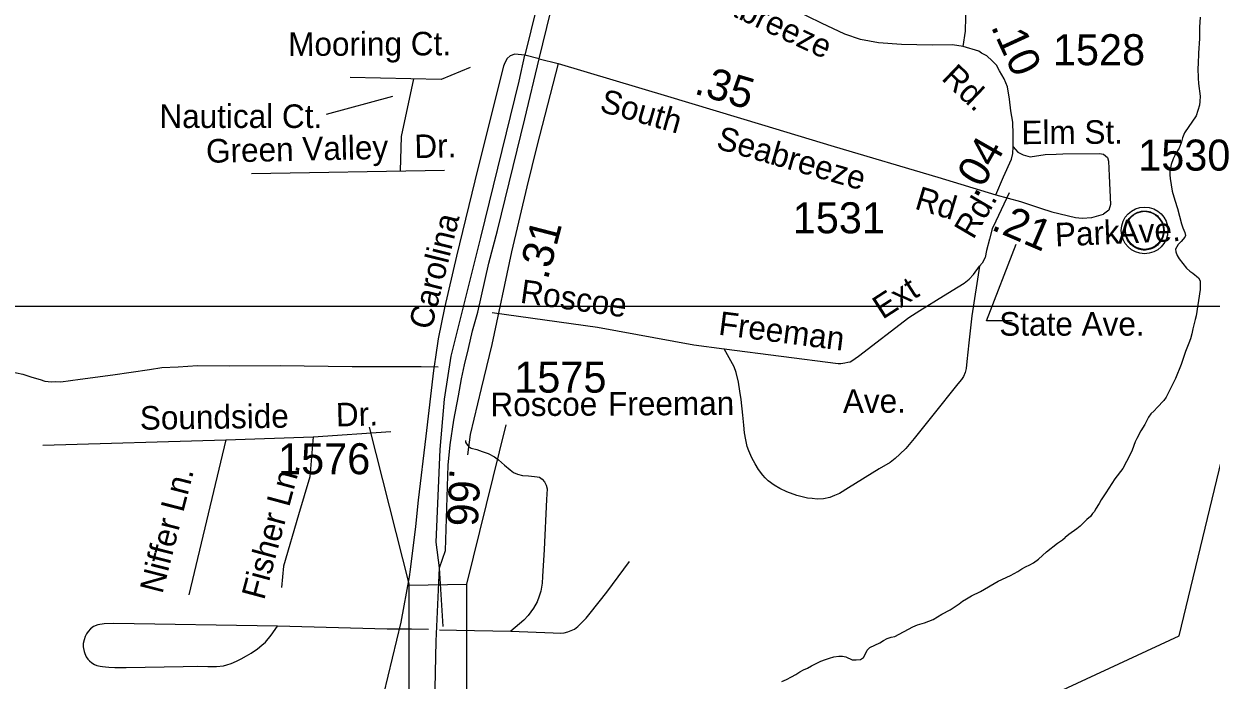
# Model space of a CAD drawing. Extents: x 2290055 to 2389491, y 66597 to 237875.
# Drawn here: x 2331660 to 2336448, y 113874 to 116521 of the extents above; entities that cross this region are included whole.
import ezdxf

# ---------------------------------------------------------------- set-up
doc = ezdxf.new("R2010")
doc.units = 0
for name, color, linetype in [('Exist Boundary Political City Limit New', 7, 'Continuous'), ('Exist Civil Demographics Community CELL', 7, 'Continuous'), ('Exist Hydrographic Island Shore', 7, 'Continuous'), ('Exist Road Non-System Type 51', 7, 'Continuous'), ('Exist Road Non-System Type 51 Label', 7, 'Continuous'), ('Exist Road Primary US Divided Attributed', 7, 'Continuous'), ('Exist Road Primary US Label', 7, 'Continuous'), ('Exist Road Primary US Mileage Hundredths English Label', 7, 'Continuous'), ('Exist Road Primary US Structure Standard Bridge CELL', 7, 'Continuous'), ('Exist Road Primary US UnDivided 4 Lane Attributed', 7, 'Continuous'), ('Exist Road Secondary Mileage Hundredths English Label', 7, 'Continuous'), ('Exist Road Secondary Type 51 Attributed', 7, 'Continuous'), ('Exist Road Secondary Type 51 Label', 7, 'Continuous'), ('Exist Road Secondary Type 51 Number Label', 7, 'Continuous'), ('Map Preparation Boundary City Limit Buffer Line', 7, 'Continuous'), ('Map Preparation Inset Cut Line', 7, 'Continuous')]:
    doc.layers.add(name, color=color, linetype=linetype)

msp = doc.modelspace()

# ---------------------------------------------------------------- linework, layer by layer
at = {"layer": 'Exist Boundary Political City Limit New'}
msp.add_lwpolyline([(2330352.2, 107963.5), (2330441, 107913.5), (2331723, 108557.6), (2331795.2, 108507.7), (2332822, 112811.2), (2334428.5, 113377.6), (2334989.2, 113572), (2335533.8, 113689.2), (2336319, 114052.8), (2336557, 115038.5), (2336580.2, 115183.5), (2339245, 115328.5)], dxfattribs=at)
at = {"layer": 'Exist Civil Demographics Community CELL'}
msp.add_lwpolyline([(2336101.6, 115700), (2336102.6, 115705.6), (2336104.3, 115712.2), (2336107.3, 115719.4), (2336110.2, 115725.1), (2336113.5, 115730.8), (2336117.3, 115736), (2336121.2, 115740.3), (2336125.8, 115744.9), (2336131.4, 115749.5), (2336136.8, 115753.2), (2336141.7, 115756), (2336146.7, 115758.5), (2336152.2, 115760.8), (2336157.8, 115762.6), (2336162.2, 115763.8), (2336167, 115764.5), (2336171.1, 115765.2), (2336177.5, 115765.5), (2336181.9, 115765.4), (2336187.6, 115765.1), (2336192.5, 115764.4), (2336197.4, 115763.4), (2336202.4, 115762), (2336207.6, 115760.1), (2336214.2, 115757.1), (2336220.5, 115753.6), (2336225.6, 115750.1), (2336230.7, 115746.1), (2336234, 115742.9), (2336238.2, 115738.6), (2336242, 115733.9), (2336245.1, 115729.3), (2336248.2, 115724.3), (2336250.7, 115719.1), (2336252.7, 115714.1), (2336254.3, 115709.1), (2336255.6, 115704.5), (2336256.6, 115698.4), (2336257.3, 115693.7), (2336257.5, 115687.7), (2336257.4, 115681.9), (2336256.8, 115676.3), (2336255.8, 115670.8), (2336254.2, 115664.6), (2336252.3, 115658.8), (2336250, 115653.7), (2336246.9, 115647.7), (2336243.6, 115642.4), (2336240.1, 115637.7), (2336235.9, 115632.9), (2336230.6, 115628), (2336225.6, 115623.9), (2336220.6, 115620.4), (2336216.3, 115617.9), (2336209.5, 115614.7), (2336202.3, 115612), (2336196.4, 115610.5), (2336189.8, 115609.2), (2336185.3, 115608.7), (2336180.8, 115608.5), (2336175.3, 115608.5), (2336171, 115608.9), (2336165.3, 115609.6), (2336159.4, 115610.9), (2336154.8, 115612.2), (2336149.7, 115614.1), (2336145.1, 115616.1), (2336141.2, 115618.3), (2336134.3, 115622.4), (2336128.8, 115626.7), (2336123.9, 115631.2), (2336119.4, 115636), (2336116.2, 115640), (2336113.2, 115644.2), (2336109.1, 115651.3), (2336107.4, 115654.8), (2336105.7, 115658.8), (2336103.1, 115667), (2336101.6, 115674.1), (2336100.9, 115679.2), (2336100.6, 115685.5), (2336100.5, 115690.2), (2336101.1, 115696.7)], close=True, dxfattribs=at)
for centre, radius in [((2336179.2, 115687.6), 94.3), ((2336178.9, 115687.9), 76.7)]:
    msp.add_circle(centre, radius, dxfattribs=at)
at = {"layer": 'Exist Hydrographic Island Shore'}
for points in [[(2336403.2, 116546.9), (2336400.5, 116507), (2336401.2, 116461.6), (2336397, 116401.8), (2336394.7, 116359.6), (2336394.5, 116341.5), (2336394.7, 116300.9), (2336396.5, 116279.8), (2336403.2, 116229.3), (2336402.5, 116207.8), (2336400, 116191.9), (2336386.5, 116149.7), (2336340.5, 116080.3), (2336332, 116061.3), (2336327.5, 116044.1), (2336318.7, 116019.6), (2336306.2, 116000), (2336294.2, 115976.5), (2336286, 115953.7), (2336281.5, 115928), (2336281.5, 115912.2), (2336282.7, 115896.6), (2336290, 115846.4), (2336301, 115809), (2336312, 115776.2), (2336328.2, 115713.9), (2336333.7, 115697.9), (2336341.2, 115679.7), (2336343.5, 115667.7), (2336341.7, 115659.7), (2336326.5, 115642.4), (2336315, 115631.4), (2336303.2, 115612.2), (2336304.5, 115601.1), (2336310.5, 115587), (2336318.5, 115572.8), (2336348.5, 115535.8), (2336361.5, 115523.6), (2336374, 115514.9), (2336397, 115496.6), (2336403, 115484.2), (2336402.7, 115449.9), (2336386.5, 115343), (2336383.2, 115328.2), (2336373.2, 115291.4), (2336369, 115270.2), (2336364, 115250.3), (2336358, 115232.9), (2336344, 115199.9), (2336327.2, 115147.7), (2336303.5, 115090.5), (2336274, 115031.4), (2336265.5, 115015.8), (2336256.2, 115002.1), (2336230.5, 114973.9), (2336217.5, 114960.4), (2336204.5, 114948.2), (2336195.5, 114934.3), (2336180.7, 114905.8), (2336164.2, 114879.3), (2336148, 114849.4), (2336140.7, 114834.7), (2336128.7, 114802.2), (2336122, 114787.1), (2336106.5, 114755.6), (2336091, 114727.7), (2336058.5, 114685.8), (2336023.5, 114629.9), (2336004.5, 114601), (2335996.5, 114587), (2335981.5, 114564.3), (2335976.5, 114554.8), (2335969.5, 114547.1), (2335960.5, 114534.3), (2335946.5, 114522), (2335919.5, 114495.3), (2335906.2, 114484.7), (2335874.2, 114462), (2335859.5, 114449.7)], [(2334836, 113932.7), (2334854.2, 113942.3), (2334874, 113951), (2334892.2, 113958.1), (2334909, 113963.7), (2334926, 113968.1), (2334946, 113971.6), (2334961.7, 113971.9), (2334974.5, 113968.5), (2335000, 113956.7), (2335015.7, 113956.1), (2335033.7, 113957.4), (2335045.7, 113965.8), (2335053.5, 113980.4), (2335060, 113994.9), (2335071.7, 114006.4), (2335112, 114024.6), (2335127, 114034.4), (2335141.7, 114042.3), (2335157, 114047.6), (2335171.7, 114050.9), (2335244.5, 114089.2), (2335263, 114097.1), (2335292.2, 114105.9), (2335309, 114111.9), (2335326.2, 114119.8), (2335362, 114140.2), (2335394.7, 114157.7), (2335432, 114182), (2335445.5, 114192.5), (2335461, 114202.9), (2335480.7, 114214.7), (2335518, 114232.3), (2335588.2, 114273.2), (2335639, 114296.1), (2335668.5, 114312.4), (2335684.2, 114323), (2335699.2, 114331.4), (2335716.5, 114339.5), (2335731.7, 114348), (2335751, 114362.5), (2335783, 114391.8), (2335828, 114427), (2335847.7, 114439.9), (2335859.5, 114449.7)], [(2334716, 113868.9), (2334735.7, 113877.6), (2334755.5, 113887.6), (2334773.2, 113897.3), (2334788.5, 113908.4), (2334803.5, 113916.7), (2334820.2, 113923.2), (2334836, 113932.7)]]:
    msp.add_lwpolyline(points, dxfattribs=at)
at = {"layer": 'Exist Road Non-System Type 51'}
for p, q in [((2333188.5, 115138.7), (2333261.9, 115138.4)), ((2333261.9, 115138.4), (2333330.1, 115138.2)), ((2333125.3, 114080.7), (2332683.1, 114091.8)), ((2333223.7, 114080), (2333125.3, 114080.7)), ((2333291.4, 114079.5), (2333223.7, 114080)), ((2333336.4, 114077.9), (2333404.1, 114076.5)), ((2333404.1, 114076.5), (2333623.6, 114071.8))]:
    msp.add_line(p, q, dxfattribs=at)
for points in [[(2333459.6, 116344.2), (2333342.8, 116296.5), (2332976.3, 116304.5)], [(2333230.8, 116298.9), (2333181.7, 116066.7), (2333177.1, 115927.2)], [(2332577.5, 115917.6), (2333356.1, 115930)], [(2335633.7, 115838.8), (2335578.8, 115724.4), (2335565.2, 115694), (2335553.4, 115651.8), (2335542.1, 115606.1), (2335536.3, 115577.9), (2335524.8, 115555.5), (2335512.8, 115543.5)], [(2334484.1, 115210.8), (2334943, 115151.5), (2334954.8, 115151.6), (2334970.5, 115153.9), (2334983.2, 115156), (2334991.3, 115158.3), (2334999.1, 115161.6), (2335026.2, 115180.4), (2335228.8, 115336.7), (2335272.7, 115365), (2335367.8, 115423.9), (2335427.4, 115460.7), (2335451.5, 115474.8), (2335471.2, 115491), (2335489.2, 115509.5), (2335512.8, 115543.5)], [(2335512.8, 115543.5), (2335482.6, 115343.1), (2335470.1, 115235), (2335463, 115158.9), (2335459.1, 115130.8), (2335455.2, 115114.9), (2335448.9, 115098.9), (2335441.5, 115086.5), (2335425.8, 115068.5), (2335324.7, 114943.4), (2335250, 114848.8), (2335216.2, 114808.4), (2335192.8, 114785.9), (2335172.8, 114767.7), (2335153.1, 114751.5), (2335109.1, 114727.1), (2334985.8, 114649.7), (2334948.3, 114627.5), (2334929.2, 114619.2), (2334910.5, 114610.9), (2334884.2, 114605.3), (2334858.6, 114604.6), (2334838.5, 114606.5), (2334820.4, 114608.7), (2334777, 114618.5), (2334736, 114633.3), (2334707.9, 114646.9), (2334685.7, 114660.8), (2334661.7, 114678.6), (2334649.4, 114690.2), (2334639.5, 114700.4), (2334622.2, 114723.3), (2334608.8, 114746.1), (2334595.7, 114771.2), (2334583.8, 114798.6), (2334576.8, 114816), (2334571.2, 114843.1), (2334565.5, 114871.4), (2334562.6, 114902.5), (2334558.7, 114943.3), (2334552, 115005.4), (2334547.7, 115039.4), (2334541.3, 115075.6), (2334532.9, 115115.3), (2334524.8, 115137.3), (2334484.1, 115210.8)], [(2333548.2, 115357), (2333973, 115297.6), (2334361.8, 115225.7), (2334484.1, 115210.8)], [(2331583.1, 115123.2), (2331600.1, 115119), (2331630.2, 115113.3), (2331656.4, 115107.7), (2331692.3, 115096), (2331726.5, 115086.2), (2331744.8, 115080.4), (2331758.6, 115078.6), (2331770.5, 115076.8), (2331788.5, 115079.2), (2331808.6, 115077.3), (2331886.6, 115088), (2332018.5, 115105.3), (2332166.3, 115126.9), (2332216.2, 115135.4), (2332282.1, 115138), (2332360, 115142.7), (2332490, 115142.3), (2332694.1, 115142.5), (2332984.1, 115139.5), (2333188.5, 115138.7)], [(2332826.2, 114855.6), (2333140.1, 114876.8)], [(2331736.3, 114821.6), (2332474.2, 114842.8), (2332826.2, 114855.6)], [(2332474.2, 114842.8), (2332325.8, 114219)], [(2332826.2, 114855.6), (2332813.5, 114694.3), (2332766.9, 114541.5), (2332707.5, 114333.6), (2332699, 114248.7)], [(2333440.4, 114840.3), (2333441.5, 114833.9), (2333445.4, 114826.8), (2333449.9, 114820.1), (2333456, 114815.1), (2333463.8, 114810.2), (2333486, 114804.5), (2333508, 114796.8), (2333531.9, 114788.9), (2333558, 114775.2), (2333574.6, 114763.3), (2333598.4, 114741.6), (2333620.9, 114721.8), (2333635, 114711.9), (2333651, 114705.6), (2333671, 114700.2), (2333695, 114698.5), (2333718.7, 114696.2), (2333729.9, 114694.6), (2333739.9, 114692.4), (2333750.3, 114684.9), (2333759.6, 114673.5), (2333765.7, 114661.3), (2333769.6, 114645.3), (2333768, 114603.3), (2333758.3, 114401), (2333751.4, 114293.1), (2333749.5, 114265.1), (2333744.2, 114232.8), (2333738.1, 114212.8), (2333730.5, 114190.5), (2333715.4, 114165.3), (2333693.6, 114135.2), (2333676, 114116.2), (2333623.6, 114071.8)], [(2333623.6, 114071.8), (2333793.8, 114065.4), (2333823.7, 114063.9), (2333838.8, 114064.8), (2333854.1, 114069), (2333867.6, 114074.2), (2333880.2, 114080.6), (2333893.6, 114090.6), (2333907.5, 114104.3), (2333927.4, 114124.8), (2333943, 114145.1), (2334010.2, 114229.8), (2334102.8, 114352.6)], [(2332683.1, 114091.8), (2332022.9, 114103.1), (2331983.9, 114101.6), (2331958.1, 114098.3), (2331941.1, 114090.4), (2331929.3, 114081.7), (2331918.8, 114070.8), (2331913.3, 114062), (2331907.2, 114050), (2331903.1, 114036.7), (2331899.8, 114022.1), (2331899.6, 114009.6), (2331900.2, 114002.1), (2331902.7, 113990.4), (2331906, 113981.7), (2331912, 113968.8), (2331918.3, 113959.8), (2331924.5, 113952.2), (2331934.7, 113944.1), (2331944.4, 113938.2), (2331954.4, 113934.3), (2331967.4, 113931.2), (2331976.9, 113929.6), (2331989.1, 113928.2), (2332002.7, 113926.7), (2332026.7, 113925), (2332054.9, 113925.5), (2332072.6, 113925.5), (2332302.8, 113930), (2332360.9, 113930.7), (2332402, 113929.7), (2332436.8, 113929.4), (2332464.9, 113932.2), (2332479.2, 113936.3), (2332496.7, 113942), (2332517.7, 113950.7), (2332536.6, 113960.9), (2332558.5, 113972.6), (2332576.1, 113983.5), (2332602.3, 114000.9), (2332620.1, 114015.1), (2332634.1, 114027.5), (2332657.9, 114056.6), (2332683.1, 114091.8)]]:
    msp.add_lwpolyline(points, dxfattribs=at)
at = {"layer": 'Exist Road Non-System Type 51 Label'}
for points in [[(2332879.8, 116156.4), (2333147.9, 116228.6)], [(2335645.5, 115322.6), (2335542.3, 115322.6), (2335661, 115632.2)]]:
    msp.add_lwpolyline(points, dxfattribs=at)
at = {"layer": 'Exist Road Primary US Divided Attributed'}
for points in [[(2334466.3, 119591.7), (2334361.5, 119167.8), (2334174.1, 118409.4), (2334050.7, 117905.9), (2333955.7, 117519.8), (2333800.5, 116886), (2333680.3, 116393.8)], [(2333738.2, 116379.2), (2333877, 116945.7)], [(2333336.7, 114327.1), (2333323.3, 114430.5), (2333338.3, 114804), (2333356.7, 115007.4), (2333383.4, 115180.9), (2333503.4, 115659.4), (2333656.8, 116289.7), (2333680.3, 116393.8)], [(2333351.2, 114090.7), (2333336.7, 114327.1), (2333360, 114397.1), (2333370.9, 114740.7), (2333379.7, 114823), (2333393.9, 114923.3), (2333412.1, 115021.2), (2333424.2, 115088.7), (2333436.3, 115145.9), (2333452.8, 115211.8), (2333469.2, 115282.4), (2333490, 115357.8), (2333535.1, 115556.2), (2333569.7, 115687.4), (2333680.6, 116137.9), (2333738.2, 116379.2)]]:
    msp.add_lwpolyline(points, dxfattribs=at)
at = {"layer": 'Exist Road Primary US Structure Standard Bridge CELL'}
for p, q in [((2333052.5, 114894.4), (2333213.3, 114257.1)), ((2333604.2, 114904.4), (2333444.8, 114261.3))]:
    msp.add_line(p, q, dxfattribs=at)
msp.add_lwpolyline([(2333444.8, 114261.3), (2333447.1, 112278.2), (2333215.5, 112274.1), (2333213.3, 114257.1)], close=True, dxfattribs=at)
at = {"layer": 'Exist Road Primary US UnDivided 4 Lane Attributed'}
msp.add_lwpolyline([(2333306.4, 113154.1), (2333311.7, 113523.4), (2333323.3, 114032), (2333336.7, 114327.1)], dxfattribs=at)
at = {"layer": 'Exist Road Secondary Type 51 Attributed'}
for points in [[(2335448.1, 116428.8), (2335404.5, 116435.8), (2335322.7, 116434.8), (2335198.9, 116436.9), (2335106.1, 116444.3), (2335033.1, 116457.5), (2334970.9, 116478), (2334876.4, 116522.8), (2334600.2, 116658.4), (2334513, 116694.4), (2334442.4, 116727.5), (2334379.2, 116754.6), (2334238, 116811.7), (2333877, 116945.7)], [(2335448.1, 116428.8), (2335456.5, 116491.4), (2335462.4, 116717.3), (2335464.9, 116869), (2335467.5, 116901.9)], [(2335649.7, 116025.1), (2335649.1, 116074.3), (2335647.3, 116124.5), (2335640.4, 116169.6), (2335634.3, 116216.8), (2335626.5, 116266.2), (2335612.7, 116299.1), (2335594.5, 116331.1), (2335581.5, 116353.7), (2335565, 116371), (2335543.4, 116391.8), (2335521.4, 116402.4), (2335510.7, 116410.4), (2335448.1, 116428.8)], [(2333680.3, 116393.8), (2333639.7, 116398.6), (2333621.3, 116391.7), (2333609.2, 116381.1), (2333598.9, 116362.5), (2333594, 116349.8), (2333491.3, 115936.9), (2333405.1, 115584.3), (2333355.7, 115375.1), (2333331.3, 115250.3), (2333319.4, 115177.3), (2333312.1, 115122.7), (2333280.7, 114857.8), (2333250.3, 114600.7), (2333239.5, 114494.1), (2333217.9, 114320.5), (2333213.2, 114291), (2333180.4, 114108.5), (2333109.7, 113818.2), (2333009.4, 113405.7)], [(2333814.4, 116360.3), (2333728.3, 116026.6), (2333688.4, 115862.9), (2333626.9, 115601.2), (2333547.5, 115227.4), (2333504, 115050.7), (2333459.1, 114864.7), (2333449, 114783.2)], [(2333738.2, 116379.2), (2333680.3, 116393.8)], [(2333738.2, 116379.2), (2333814.4, 116360.3)], [(2333814.4, 116360.3), (2334255, 116228.5), (2334634.4, 116113.9), (2334927.7, 116026.1), (2335345, 115901.8), (2335579.9, 115830.9)], [(2335579.9, 115830.9), (2335610, 115903.6), (2335642.1, 115974.6), (2335647.3, 115998), (2335649.7, 116025.1)], [(2335649.7, 116025.1), (2335668.1, 116003.2), (2335689.8, 115991.9), (2335718.4, 115984.1), (2335778.1, 115993.7), (2335823.2, 115995.4), (2335849.6, 115996.2), (2335996.8, 115997), (2336013, 115994.4), (2336029.8, 115981.8), (2336033.5, 115966.6), (2336036.8, 115907.6), (2336041.5, 115791.4), (2336034.6, 115769.7), (2336013.4, 115752.6)], [(2335579.9, 115830.9), (2335678.5, 115803.9), (2335759.1, 115777.1), (2335804.5, 115762.3), (2335900.8, 115739.8), (2335927.2, 115736.8), (2335966, 115739.4), (2336013.4, 115752.6)]]:
    msp.add_lwpolyline(points, dxfattribs=at)
at = {"layer": 'Map Preparation Boundary City Limit Buffer Line'}
msp.add_lwpolyline([(2330352.2, 107963.5), (2330441, 107913.5), (2331723, 108557.6), (2331795.2, 108507.7), (2332822, 112811.2), (2334428.5, 113377.6), (2334989.2, 113572), (2335533.8, 113689.2), (2336319, 114052.8), (2336557, 115038.5), (2336580.2, 115183.5), (2339245, 115328.5)], dxfattribs=at)
at = {"layer": 'Map Preparation Inset Cut Line'}
for points in [[(2318953.4, 149726.2), (2325417.5, 149726.2), (2346393.7, 149726.2), (2338303.7, 115381.1), (2324894.8, 115381.1)], [(2327293.1, 115381.1), (2326421, 108601.1), (2323940.9, 84753.9), (2319662, 79548.4), (2319961.8, 76608.6), (2326693.5, 76608.6), (2329528, 82750.7), (2336452.5, 105360.7), (2339748.2, 115381.1)]]:
    msp.add_lwpolyline(points, close=True, dxfattribs=at)

# ---------------------------------------------------------------- texts
at = {"layer": 'Exist Road Non-System Type 51 Label'}
for s, rotation, p in [('Mooring Ct.', 0.2364, (2332726.1, 116390.8)), ('Green Valley   Dr.', 1.2717, (2332395.7, 115960)), ('Rd.', 59.5424, (2335488.1, 115647.7)), ('Park', 2.5456, (2335819.8, 115622.6)), ('Ave.', 2.5456, (2336072.5, 115633.8)), ('Ext', 32.854, (2335122.7, 115326.8)), ('Roscoe', 351.9618, (2333658.1, 115396.6)), ('Freeman', 352.6314, (2334458, 115267.7)), ('Roscoe ', 0.3403, (2333541.7, 114938.3)), ('Freeman', 0.3403, (2334016.3, 114941)), ('Ave.', 0.3403, (2334962.8, 114951.5)), ('Soundside ', 0.83, (2332128.5, 114883.9)), ('Dr.', 1.6202, (2332919.5, 114896.9)), ('Fisher Ln.', 74.9183, (2332628.5, 114194.3)), ('Niffer Ln.', 75.6075, (2332218.3, 114219.5))]:
    msp.add_text(s, height=95, rotation=rotation, dxfattribs=at).set_placement(p)
for s, p in [('Nautical Ct.', (2332206.6, 116100.5)), ('State Ave.', (2335593.3, 115263.3))]:
    msp.add_text(s, height=95, dxfattribs=at).set_placement(p)
at = {"layer": 'Exist Road Primary US Label'}
msp.add_text('Carolina', height=95, rotation=76.0512, dxfattribs=at).set_placement((2333303.4, 115282.9))
at = {"layer": 'Exist Road Primary US Mileage Hundredths English Label'}
msp.add_text('.66', height=125, rotation=267.0915, dxfattribs=at).set_placement((2333377.3, 114730.2))
at = {"layer": 'Exist Road Secondary Mileage Hundredths English Label'}
for s, rotation, p in [('.10', 294.6407, (2335557.8, 116509.7)), ('.35', 343.4462, (2334358.6, 116240.2)), ('.04', 60.3472, (2335502.1, 115814.2)), ('.21', 336.7959, (2335556, 115692.3)), ('.31', 75.4825, (2333772.5, 115485.3))]:
    msp.add_text(s, height=125, rotation=rotation, dxfattribs=at).set_placement(p)
at = {"layer": 'Exist Road Secondary Type 51 Label'}
for s, rotation, p in [('Seabreeze', 334.8956, (2334333.2, 116637.8)), ('Rd.', 316.2553, (2335356.3, 116297.4)), ('South', 344.0152, (2333977.5, 116168.6)), ('Elm St.', 0.3115, (2335682.6, 116035.1)), ('Seabreeze', 343.8743, (2334447.6, 116019.1)), ('Rd', 343.3376, (2335248, 115775.8))]:
    msp.add_text(s, height=95, rotation=rotation, dxfattribs=at).set_placement(p)
at = {"layer": 'Exist Road Secondary Type 51 Number Label'}
for s, p in [('1528', (2335809.3, 116353.5)), ('1530', (2336153.2, 115928.7)), ('1531', (2334760.4, 115676)), ('1575', (2333637.4, 115033.7)), ('1576', (2332685.1, 114704.7))]:
    msp.add_text(s, height=125, dxfattribs=at).set_placement(p)

doc.saveas('drawing.dxf')
